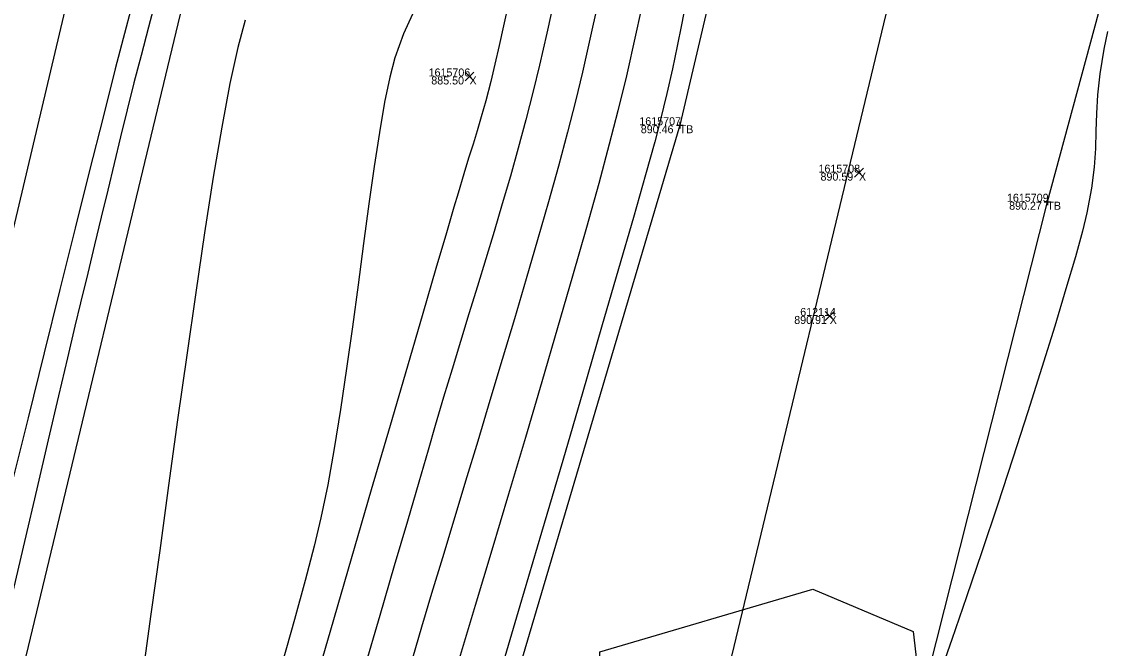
# Model space of a CAD drawing. Extents: x 1957117 to 1971063, y 701601 to 715861.
# Drawn here: x 1962877.33 to 1962924.68, y 704314.53 to 704341.95 of the extents above; entities that cross this region are included whole.
import ezdxf

# ---------------------------------------------------------------- set-up
doc = ezdxf.new("R2010")
doc.units = 0
for name, color, linetype in [('AP_X_Lights', 7, 'Continuous'), ('DT_X_Break_Line', 7, 'Continuous'), ('DT_X_Contour_Major', 7, 'Continuous'), ('DT_X_Contour_Minor', 7, 'Continuous'), ('GE_X_CL_20', 7, 'Continuous'), ('HY_X_Water_Edge', 7, 'Continuous'), ('PV_P_Drive', 7, 'Continuous'), ('PV_P_Shoulder', 7, 'Continuous'), ('RS_Raster1', 7, 'Continuous'), ('RW_X_Esmt_RR', 7, 'Continuous'), ('SC_Scratch1', 7, 'Continuous'), ('VG_X_Tree_Line_Rt', 7, 'Continuous')]:
    doc.layers.add(name, color=color, linetype=linetype)

msp = doc.modelspace()

# ---------------------------------------------------------------- linework, layer by layer
at = {"layer": 'AP_X_Lights'}
for p, q in [((1962896.722, 704339.354), (1962897.11, 704339.744)), ((1962896.722, 704339.744), (1962897.11, 704339.354)), ((1962913.754, 704335.146), (1962914.142, 704335.536)), ((1962913.754, 704335.536), (1962914.142, 704335.146)), ((1962912.476, 704328.877), (1962912.864, 704329.267)), ((1962912.476, 704329.267), (1962912.864, 704328.877))]:
    msp.add_line(p, q, dxfattribs=at)
at = {"layer": 'DT_X_Break_Line'}
for points in [[(1962854.549, 704243.654), (1962868.069, 704295.231), (1962879.669, 704344.313), (1962892.757, 704392.318), (1962905.964, 704443.142), (1962917.718, 704492.375), (1962926.962, 704538.336), (1962936.778, 704587.265), (1962949.215, 704630.669), (1962963.968, 704683.754), (1962972.038, 704733.348), (1962988.206, 704780.999), (1962994.689, 704830.943), (1963004.932, 704879.138), (1963021.822, 704927.498), (1963031.944, 704976.286), (1963045.21, 705027.355), (1963059.618, 705072.384), (1963067.267, 705121.949)], [(1962898.502, 704228.866), (1962909.862, 704285.214), (1962922.189, 704334.068), (1962935.173, 704382.087), (1962941.87, 704432.109), (1962957.87, 704479.084), (1962969.135, 704528.545), (1962980.039, 704577.268), (1962992.03, 704625.595), (1963002.128, 704674.596), (1963014.376, 704720.299), (1963028.69, 704776.02), (1963039.098, 704819.371), (1963047.66, 704863.952), (1963060.514, 704915.168), (1963074.044, 704961.959), (1963084.157, 705010.121), (1963093.862, 705036.7), (1963097.69, 705062.728), (1963110.134, 705110.941)], [(1963081.686, 705067.168), (1963070.617, 705018.992), (1963060.629, 704969.66), (1963044.793, 704921.859), (1963033.624, 704869.219), (1963022.038, 704824.561), (1963012.554, 704778.141), (1962998.858, 704727.004), (1962987.967, 704677.611), (1962975.675, 704626.305), (1962966.447, 704580.213), (1962950.262, 704533.092), (1962939.515, 704481.257), (1962926.044, 704436.037), (1962917.68, 704386.811), (1962906.11, 704337.415), (1962892.064, 704289.931), (1962881.011, 704234.451)]]:
    msp.add_lwpolyline(points, dxfattribs=at)
at = {"layer": 'DT_X_Contour_Major'}
for points in [[(1962906.364, 704342.716), (1962906.19, 704341.806), (1962906.003, 704340.869), (1962905.793, 704339.877), (1962905.549, 704338.8), (1962905.261, 704337.612), (1962905.015, 704336.682), (1962904.616, 704335.252), (1962904.085, 704333.384), (1962903.438, 704331.138), (1962902.695, 704328.576), (1962901.873, 704325.759), (1962900.992, 704322.748), (1962900.07, 704319.604), (1962899.124, 704316.389), (1962898.173, 704313.163)], [(1962906.364, 704342.716), (1962906.19, 704341.806), (1962906.003, 704340.869), (1962905.793, 704339.877), (1962905.549, 704338.8), (1962905.261, 704337.612), (1962905.015, 704336.682), (1962904.616, 704335.252), (1962904.085, 704333.384), (1962903.438, 704331.138), (1962902.695, 704328.576), (1962901.873, 704325.759), (1962900.992, 704322.748), (1962900.07, 704319.604), (1962899.124, 704316.389), (1962898.173, 704313.163)], [(1962894.419, 704342.273), (1962894.026, 704341.413), (1962893.653, 704340.369), (1962893.43, 704339.519), (1962893.207, 704338.419), (1962892.982, 704337.104), (1962892.754, 704335.612), (1962892.522, 704333.979), (1962892.286, 704332.242), (1962892.044, 704330.437), (1962891.796, 704328.601), (1962891.54, 704326.771), (1962891.275, 704324.982), (1962891.001, 704323.273), (1962890.717, 704321.679), (1962890.422, 704320.237), (1962890.125, 704318.998), (1962889.734, 704317.503), (1962889.262, 704315.785), (1962888.72, 704313.88)], [(1962894.419, 704342.273), (1962894.026, 704341.413), (1962893.653, 704340.369), (1962893.43, 704339.519), (1962893.207, 704338.419), (1962892.982, 704337.104), (1962892.754, 704335.612), (1962892.522, 704333.979), (1962892.286, 704332.242), (1962892.044, 704330.437), (1962891.796, 704328.601), (1962891.54, 704326.771), (1962891.275, 704324.982), (1962891.001, 704323.273), (1962890.717, 704321.679), (1962890.422, 704320.237), (1962890.125, 704318.998), (1962889.734, 704317.503), (1962889.262, 704315.785), (1962888.72, 704313.88)], [(1962924.825, 704341.511), (1962924.651, 704340.747), (1962924.479, 704339.668), (1962924.383, 704338.745), (1962924.337, 704337.925), (1962924.313, 704337.159), (1962924.287, 704336.393), (1962924.229, 704335.577), (1962924.115, 704334.659), (1962923.917, 704333.588), (1962923.722, 704332.787), (1962923.412, 704331.662), (1962923.002, 704330.259), (1962922.508, 704328.628), (1962921.946, 704326.818), (1962921.331, 704324.877), (1962920.679, 704322.854), (1962920.005, 704320.797), (1962919.326, 704318.756), (1962918.657, 704316.778), (1962918.013, 704314.913), (1962917.41, 704313.209)], [(1962924.825, 704341.511), (1962924.651, 704340.747), (1962924.479, 704339.668), (1962924.383, 704338.745), (1962924.337, 704337.925), (1962924.313, 704337.159), (1962924.287, 704336.393), (1962924.229, 704335.577), (1962924.115, 704334.659), (1962923.917, 704333.588), (1962923.722, 704332.787), (1962923.412, 704331.662), (1962923.002, 704330.259), (1962922.508, 704328.628), (1962921.946, 704326.818), (1962921.331, 704324.877), (1962920.679, 704322.854), (1962920.005, 704320.797), (1962919.326, 704318.756), (1962918.657, 704316.778), (1962918.013, 704314.913), (1962917.41, 704313.209)]]:
    msp.add_lwpolyline(points, dxfattribs=at)
at = {"layer": 'DT_X_Contour_Minor'}
for points in [[(1962902.699, 704343.541), (1962902.241, 704341.448), (1962901.856, 704339.74), (1962901.554, 704338.473), (1962901.203, 704337.108), (1962900.806, 704335.63), (1962900.368, 704334.057), (1962899.897, 704332.406), (1962899.4, 704330.694), (1962898.882, 704328.94), (1962898.351, 704327.16), (1962897.813, 704325.372), (1962897.276, 704323.594), (1962896.745, 704321.843), (1962896.228, 704320.136), (1962895.731, 704318.491), (1962895.26, 704316.926), (1962894.824, 704315.458), (1962894.428, 704314.104)], [(1962902.699, 704343.541), (1962902.241, 704341.448), (1962901.856, 704339.74), (1962901.554, 704338.473), (1962901.203, 704337.108), (1962900.806, 704335.63), (1962900.368, 704334.057), (1962899.897, 704332.406), (1962899.4, 704330.694), (1962898.882, 704328.94), (1962898.351, 704327.16), (1962897.813, 704325.372), (1962897.276, 704323.594), (1962896.745, 704321.843), (1962896.228, 704320.136), (1962895.731, 704318.491), (1962895.26, 704316.926), (1962894.824, 704315.458), (1962894.428, 704314.104)], [(1962883.213, 704342.986), (1962882.873, 704341.709), (1962882.552, 704340.472), (1962882.244, 704339.266), (1962881.948, 704338.084), (1962881.66, 704336.914), (1962881.377, 704335.748), (1962881.095, 704334.577), (1962880.811, 704333.391), (1962880.521, 704332.181), (1962880.223, 704330.938), (1962879.912, 704329.652), (1962879.665, 704328.62), (1962879.339, 704327.246), (1962878.946, 704325.574), (1962878.495, 704323.647), (1962877.995, 704321.508), (1962877.455, 704319.201), (1962876.887, 704316.768)], [(1962883.213, 704342.986), (1962882.873, 704341.709), (1962882.552, 704340.472), (1962882.244, 704339.266), (1962881.948, 704338.084), (1962881.66, 704336.914), (1962881.377, 704335.748), (1962881.095, 704334.577), (1962880.811, 704333.391), (1962880.521, 704332.181), (1962880.223, 704330.938), (1962879.912, 704329.652), (1962879.665, 704328.62), (1962879.339, 704327.246), (1962878.946, 704325.574), (1962878.495, 704323.647), (1962877.995, 704321.508), (1962877.455, 704319.201), (1962876.887, 704316.768)], [(1962882.295, 704343.207), (1962881.897, 704341.703), (1962881.425, 704339.878), (1962880.89, 704337.775), (1962880.3, 704335.438), (1962879.668, 704332.911), (1962879.002, 704330.235), (1962878.314, 704327.455), (1962877.613, 704324.614), (1962876.91, 704321.755)], [(1962882.295, 704343.207), (1962881.897, 704341.703), (1962881.425, 704339.878), (1962880.89, 704337.775), (1962880.3, 704335.438), (1962879.668, 704332.911), (1962879.002, 704330.235), (1962878.314, 704327.455), (1962877.613, 704324.614), (1962876.91, 704321.755)], [(1962900.652, 704343.043), (1962900.296, 704341.439), (1962899.976, 704340.047), (1962899.7, 704338.903), (1962899.379, 704337.65), (1962899.047, 704336.414), (1962898.704, 704335.191), (1962898.353, 704333.978), (1962897.996, 704332.773), (1962897.632, 704331.571), (1962897.265, 704330.37), (1962896.895, 704329.167), (1962896.525, 704327.959), (1962896.155, 704326.743), (1962895.787, 704325.516), (1962895.422, 704324.274), (1962895.112, 704323.207), (1962894.701, 704321.801), (1962894.201, 704320.097), (1962893.628, 704318.14), (1962892.992, 704315.972), (1962892.309, 704313.636)], [(1962900.652, 704343.043), (1962900.296, 704341.439), (1962899.976, 704340.047), (1962899.7, 704338.903), (1962899.379, 704337.65), (1962899.047, 704336.414), (1962898.704, 704335.191), (1962898.353, 704333.978), (1962897.996, 704332.773), (1962897.632, 704331.571), (1962897.265, 704330.37), (1962896.895, 704329.167), (1962896.525, 704327.959), (1962896.155, 704326.743), (1962895.787, 704325.516), (1962895.422, 704324.274), (1962895.112, 704323.207), (1962894.701, 704321.801), (1962894.201, 704320.097), (1962893.628, 704318.14), (1962892.992, 704315.972), (1962892.309, 704313.636)], [(1962904.618, 704343.353), (1962904.182, 704341.36), (1962903.776, 704339.577), (1962903.407, 704338.042), (1962903.031, 704336.585), (1962902.567, 704334.87), (1962902.028, 704332.934), (1962901.425, 704330.816), (1962900.771, 704328.554), (1962900.079, 704326.185), (1962899.36, 704323.748), (1962898.627, 704321.28), (1962897.893, 704318.819), (1962897.169, 704316.403), (1962896.468, 704314.07)], [(1962904.618, 704343.353), (1962904.182, 704341.36), (1962903.776, 704339.577), (1962903.407, 704338.042), (1962903.031, 704336.585), (1962902.567, 704334.87), (1962902.028, 704332.934), (1962901.425, 704330.816), (1962900.771, 704328.554), (1962900.079, 704326.185), (1962899.36, 704323.748), (1962898.627, 704321.28), (1962897.893, 704318.819), (1962897.169, 704316.403), (1962896.468, 704314.07)], [(1962898.606, 704342.685), (1962898.409, 704341.761), (1962898.217, 704340.897), (1962898.03, 704340.089), (1962897.847, 704339.333), (1962897.628, 704338.486), (1962897.434, 704337.785), (1962897.252, 704337.172), (1962897.071, 704336.59), (1962896.88, 704335.98), (1962896.665, 704335.284), (1962896.417, 704334.444), (1962896.238, 704333.831), (1962895.911, 704332.714), (1962895.452, 704331.147), (1962894.878, 704329.184), (1962894.204, 704326.879), (1962893.446, 704324.286), (1962892.622, 704321.459), (1962891.746, 704318.452), (1962890.836, 704315.32), (1962889.907, 704312.115)], [(1962898.606, 704342.685), (1962898.409, 704341.761), (1962898.217, 704340.897), (1962898.03, 704340.089), (1962897.847, 704339.333), (1962897.628, 704338.486), (1962897.434, 704337.785), (1962897.252, 704337.172), (1962897.071, 704336.59), (1962896.88, 704335.98), (1962896.665, 704335.284), (1962896.417, 704334.444), (1962896.238, 704333.831), (1962895.911, 704332.714), (1962895.452, 704331.147), (1962894.878, 704329.184), (1962894.204, 704326.879), (1962893.446, 704324.286), (1962892.622, 704321.459), (1962891.746, 704318.452), (1962890.836, 704315.32), (1962889.907, 704312.115)], [(1962887.1, 704342.015), (1962886.781, 704340.819), (1962886.441, 704339.241), (1962886.085, 704337.33), (1962885.714, 704335.136), (1962885.333, 704332.708), (1962884.944, 704330.097), (1962884.549, 704327.351), (1962884.154, 704324.522), (1962883.759, 704321.659), (1962883.369, 704318.81), (1962882.986, 704316.028), (1962882.613, 704313.36)], [(1962887.1, 704342.015), (1962886.781, 704340.819), (1962886.441, 704339.241), (1962886.085, 704337.33), (1962885.714, 704335.136), (1962885.333, 704332.708), (1962884.944, 704330.097), (1962884.549, 704327.351), (1962884.154, 704324.522), (1962883.759, 704321.659), (1962883.369, 704318.81), (1962882.986, 704316.028), (1962882.613, 704313.36)]]:
    msp.add_lwpolyline(points, dxfattribs=at)
at = {"layer": 'GE_X_CL_20'}
msp.add_lwpolyline([(1963418.3, 706437.397), (1962895.621, 704261.062)], dxfattribs=at)
at = {"layer": 'HY_X_Water_Edge'}
msp.add_spline([(1963191.723, 701994.048), (1963062.047, 702441.167), (1962863.491, 703169.356), (1962827.53, 703438.691), (1962823.213, 703537.412), (1962817.962, 703593.874), (1962817.97, 703697.316), (1962828.582, 703804.235), (1962836.461, 703844.734), (1962850.687, 703896.004), (1962867.251, 703938.846), (1962873.848, 703992.355), (1962884.135, 704091.371), (1962891.241, 704140.854), (1962897.382, 704180.529), (1962905.467, 704230.979), (1962943.949, 704328.022), (1962948.537, 704378.842), (1962964.114, 704426.264), (1963004.885, 704570.73), (1963042.054, 704716.522), (1963062.038, 704814.417), (1963072.171, 704860.237), (1963090.023, 704956.798), (1963107.066, 705031.783), (1963133.773, 705105.742), (1963148.685, 705206.74), (1963175.48, 705301.059), (1963191.635, 705353.417), (1963210.988, 705447.286), (1963219.532, 705497.27), (1963230.124, 705549.475), (1963251.052, 705591.159), (1963275.289, 705693.429), (1963292.982, 705784.032), (1963302.841, 705839.645), (1963335.126, 705936.766), (1963359.752, 706046.75), (1963389.133, 706177.299), (1963417.827, 706273.456), (1963475.868, 706451.902), (1963533.782, 706640.53), (1963553.86, 706696.984), (1963580.184, 706715.425), (1963609.172, 706718.73), (1963617.062, 706714.691), (1963619.447, 706694.678), (1963564.282, 706533.07), (1963531.853, 706395.229), (1963434.4, 706006.96), (1963354.09, 705679.186), (1963237.513, 705206.07), (1963167.369, 704892.962), (1963059.145, 704434.176), (1962907.914, 703908.742), (1962877.458, 703703.326), (1962898.357, 703412.121), (1962942.65, 703052.267), (1963048.963, 702674.866), (1963191.468, 702189.666), (1963245.396, 702019.832)], degree=3, dxfattribs=at)
at = {"layer": 'PV_P_Drive'}
for p, q in [((1962905.964, 704337.415), (1962906.256, 704337.415)), ((1962906.11, 704337.561), (1962906.11, 704337.269)), ((1962906.11, 704337.415), (1962906.11, 704337.415)), ((1962922.043, 704334.068), (1962922.335, 704334.068)), ((1962922.189, 704334.214), (1962922.189, 704333.922)), ((1962922.189, 704334.068), (1962922.189, 704334.068))]:
    msp.add_line(p, q, dxfattribs=at)
at = {"layer": 'RW_X_Esmt_RR'}
msp.add_lwpolyline([(1962866.45, 704268.068), (1963123.345, 705337.727), (1963135.496, 705336.937), (1963400.797, 706441.601)], dxfattribs=at)
at = {"layer": 'VG_X_Tree_Line_Rt'}
msp.add_lwpolyline([(1962905.144, 704273.859), (1962902.257, 704283.79), (1962905.432, 704289.628), (1962907.476, 704297.559), (1962902.869, 704306.844), (1962902.615, 704314.373), (1962911.932, 704317.119), (1962916.321, 704315.26), (1962916.969, 704309.597), (1962912.085, 704304.301), (1962913.434, 704299.015), (1962919.691, 704297.575), (1962933.48, 704298.79), (1962939.276, 704304.053), (1962945.172, 704308.576), (1962954.57, 704309.991), (1962967.739, 704310.411)], dxfattribs=at)

# ---------------------------------------------------------------- texts
at = {"layer": 'PV_P_Shoulder'}
for s, p in [('885.50', (1962895.246, 704339.199)), ('890.46', (1962904.407, 704337.065)), ('890.59', (1962912.267, 704334.991)), ('890.27', (1962920.516, 704333.718)), ('890.91', (1962911.118, 704328.722))]:
    msp.add_text(s, height=0.35, dxfattribs=at).set_placement(p)
at = {"layer": 'RS_Raster1'}
for s, p in [('1615706', (1962895.128, 704339.549)), ('1615707', (1962904.344, 704337.415)), ('1615708', (1962912.179, 704335.341)), ('1615709', (1962920.42, 704334.068)), ('612114', (1962911.381, 704329.072))]:
    msp.add_text(s, height=0.35, dxfattribs=at).set_placement(p)
at = {"layer": 'SC_Scratch1'}
for s, p in [('X', (1962896.916, 704339.199)), ('TB', (1962906.11, 704337.065)), ('X', (1962913.948, 704334.991)), ('TB', (1962922.189, 704333.718)), ('X', (1962912.67, 704328.722))]:
    msp.add_text(s, height=0.35, dxfattribs=at).set_placement(p)

doc.saveas('drawing.dxf')
